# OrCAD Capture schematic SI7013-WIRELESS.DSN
size B; title: Si7013 wireless postage stamp; rev: 1.0; note: Si7013 Postage Stamp
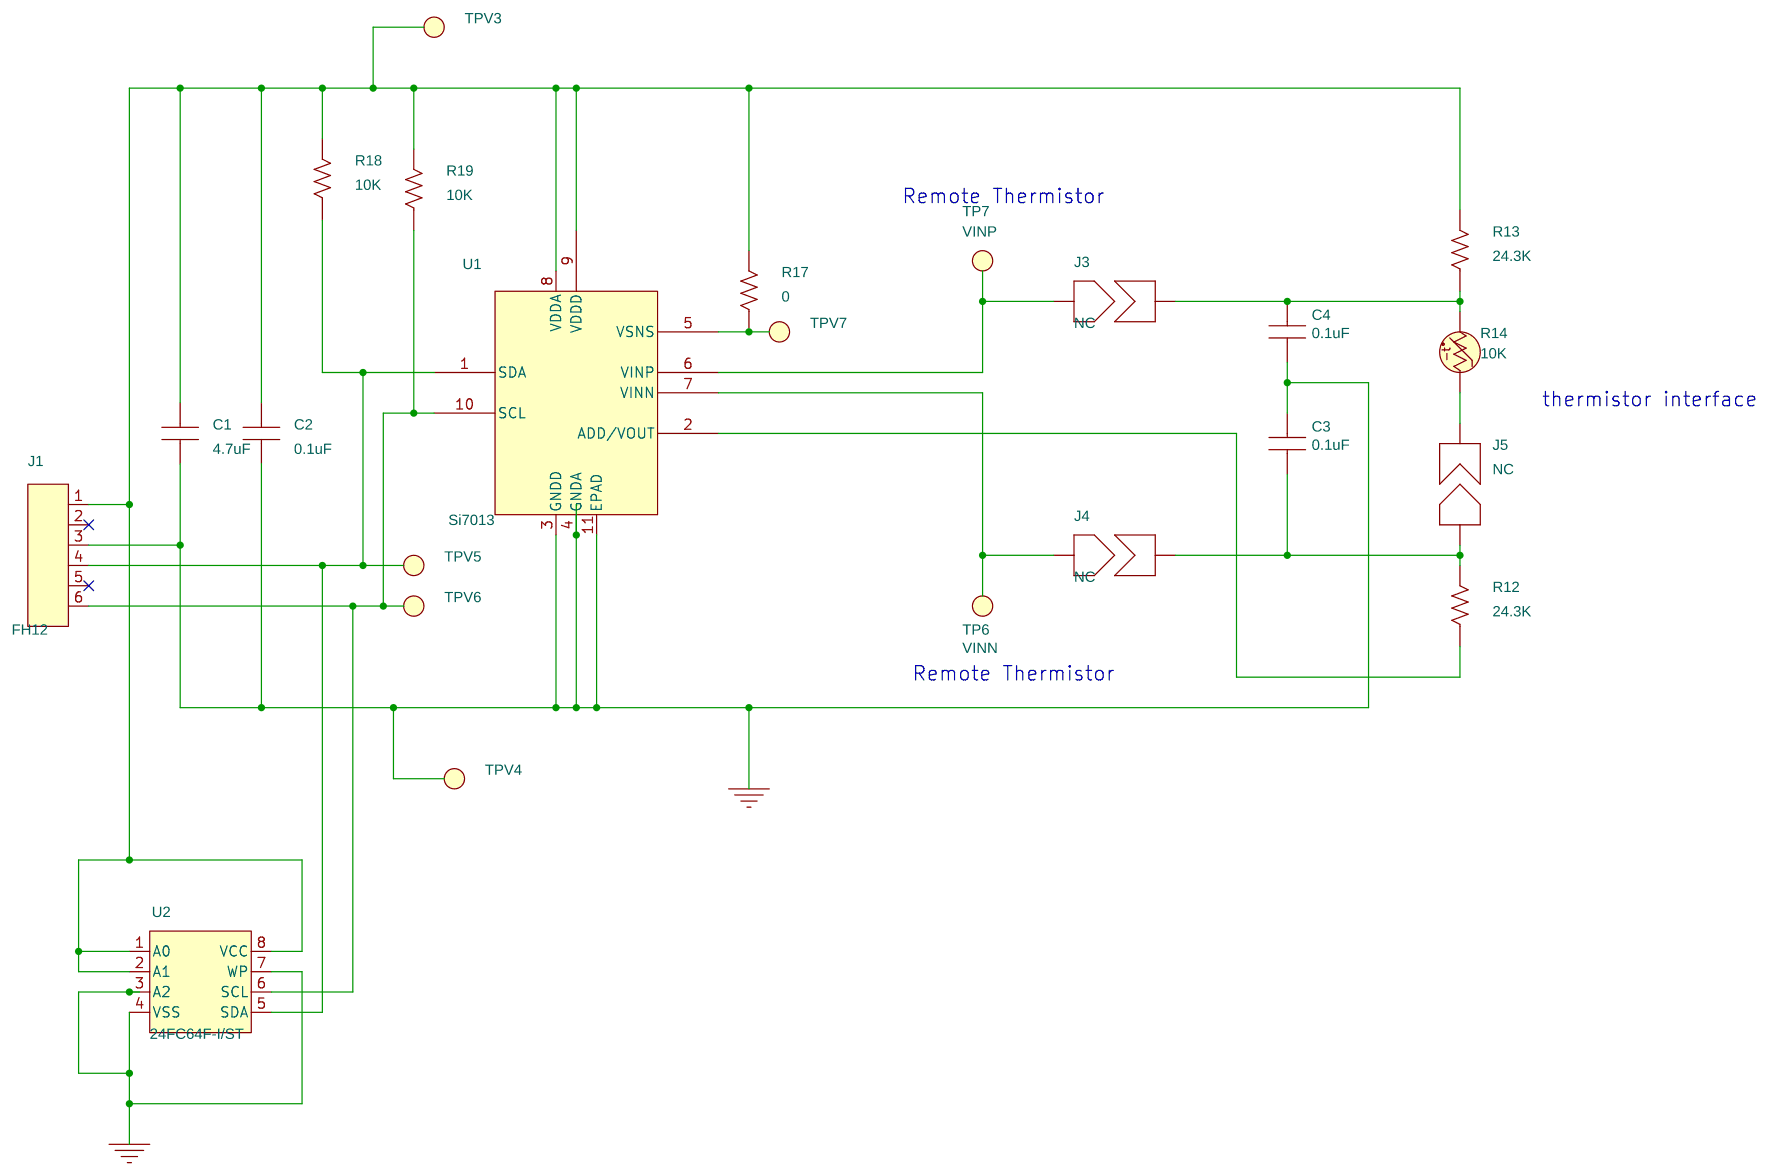
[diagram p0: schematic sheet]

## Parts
C1  4.7uF  [C0603]
C2  0.1uF  [C0402]
C3  0.1uF  [C0402]
C4  0.1uF  [C0402]
J1  FH12  [CONN6N-FPC/FFC-P0.5]
J3  NC  [SB0402-NC]
J4  NC  [SB0402-NC]
J5  NC  [SB0402-NC]
R12  24.3K  [R0603]
R13  24.3K  [R0603]
R14  10K  [R0603]
R17  0  [R0402]
R18  10K  [R0402]
R19  10K  [R0402]
TP6  BLACK  [TESTPOINT]
TP7  BLACK  [TESTPOINT]
TPV3  TPV  [VIA-TP]
TPV4  TPV  [VIA-TP]
TPV5  TPV  [VIA-TP]
TPV6  TPV  [VIA-TP]
TPV7  TPV  [VIA-TP]
U1  Si7013  [DFN10M3X3P0.5E1.4X2.6]
U2  24FC64F-I/ST  [TSSOP8N6.4P0.65]

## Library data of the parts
C1 = CAP_NP: CAP, 4.7uF, 6.3V, ±10%, X5R, 0603; Manufacturer: Venkel; ManufacturerPN: C0603X5R6R3-475K; Part_Type: CAP/NP; SiLabsPN: C0603X5R6R3-475K; Tolerance: ±10%; Type: X5R; Voltage: 6.3V; Datasheet: PID_C.pdf
C2 = CAP_NP: CAP, 0.1uF, 10V, ±10%, X7R, 0402; Manufacturer: Venkel; ManufacturerPN: C0402X7R100-104K; Part_Type: CAP/NP; SiLabsPN: C0402X7R100-104K; Tolerance: ±10%; Type: X7R; Voltage: 10V; Datasheet: PID_C.pdf
C3 C4 = CAP_NP: CAP, 0.1uF, 10V, ±20%, X7R, 0402; Manufacturer: Venkel; ManufacturerPN: C0402X7R100-104M; SiLabsPN: C0402X7R100-104M; Tolerance: ±20%; Type: X7R; Voltage: 10V; Datasheet: PID_C.pdf
J1 = CON6: CONN, 6-PIN , FPC/FFC, BOTTOM CONTACT, 0.5MM PITCH, SMD; Manufacturer: HIROSE; ManufacturerPN: FH12-6S-0.5SH(55); Part_Type: CON/MODULAR; SiLabsPN: FH12-6S-0.5SH(55); Datasheet: e58605370.pdf
J3-J5 = SolderBump: SOLDER BUMP JUMPER, NC, 0402; Manufacturer: N/A; ManufacturerPN: N/A; Type: PCB Feature
R12 R13 = RES: RES, 24.3K, 1/16W, ±1%, ThickFilm, 0603; Manufacturer: Venkel; ManufacturerPN: CR0603-16W-2432F; Rating: 1/16W; SiLabsPN: CR0603-16W-2432F; Tolerance: ±1%; Type: ThickFilm; Datasheet: PID_CR.pdf
R14 = Thermistor: Thermistor, 10K, ±1%, 0603; Manufacturer: Murata; ManufacturerPN: NCP18XH103F03RB; SiLabsPN: NCP18XH103F03RB; Tolerance: ±1%; Type: NTC; Datasheet: r44e.pdf
R17 = RES: RES, 0 Ohm, 1A, ThickFilm, 0402; Manufacturer: Venkel; ManufacturerPN: CR0402-16W-000; Rating: 1A; SiLabsPN: CR0402-16W-000; Type: ThickFilm; Datasheet: PID_CR.pdf
R18 R19 = RES: RES, 10K, 1/16W, ±1%, ThickFilm, 0402; Manufacturer: Venkel; ManufacturerPN: CR0402-16W-1002F; Rating: 1/16W; SiLabsPN: TMP-3686; Tolerance: ±1%; Type: ThickFilm; Datasheet: PID_CR.pdf
TP6 = TEST_POINT: TESTPOINT, BLACK, PTH; Manufacturer: Kobiconn; ManufacturerPN: 151-203-RC; SiLabsPN: 151-203; Silk: VINN; Type: Loop; Datasheet: KC-300780.pdf
TP7 = TEST_POINT: TESTPOINT, BLACK, PTH; Manufacturer: Kobiconn; ManufacturerPN: 151-203-RC; SiLabsPN: 151-203; Silk: VINP; Type: Loop; Datasheet: KC-300780.pdf
TPV3-TPV7 = TPV: TESTPOINT Via; Manufacturer: N/A; ManufacturerPN: N/A; Type: PCB Feature
U1 = Si7013: IC, SENSOR, HUMIDITY, DFN10; Manufacturer: SiLabs; ManufacturerPN: Si7013-A-GM; SiLabsPN: TMP-2779; Type: Sensor; Voltage: +4.2V; Datasheet: Si7013 Rev 0 2 draft 3 5 2013.pdf
U2 = 24FC64: IC, EEPROM, I2C, 64kb (8k x 8bit), 3 ADDR, 1MHz, TSSOP8; Manufacturer: Microchip; Type: I2C; Voltage: 3.3V; Datasheet: Microchip_24FC64.pdf

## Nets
GND: C1.1 C2.1 C3.1 C4.2 J1.3 TPV4.1(Point) U1.3(GNDD) U1.4(GNDA) U1.11(EPAD) U2.3(A2) U2.4(VSS) U2.7(WP)
N16761461: C1.2 C2.2 J1.1 R13.2 R17.2 R18.2 R19.2 TPV3.1(Point) U1.8(VDDA) U1.9(VDDD) U2.1(A0) U2.2(A1) U2.8(VCC)
N16761469: J1.4 R18.1 TPV5.1(Point) U1.1(SDA) U2.5(SDA)
N16761585: J1.6 R19.1 TPV6.1(Point) U1.10(SCL) U2.6(SCL)
N16768426: C4.1 J3.2(IO2) R13.1 R14.2
N16768430: C3.2 J4.2(IO2) J5.1(IO1) R12.2
N16768492: J5.2(IO2) R14.1
N16768496: R12.1 U1.2(ADD/VOUT)
N16768520: R17.1 TPV7.1(Point) U1.5(VSNS)
N16768726: J3.1(IO1) TP7.1(Point) U1.6(VINP)
N16768742: J4.1(IO1) TP6.1(Point) U1.7(VINN)

Not connected (* = marked no-connect by the designer): J1 2* 5*

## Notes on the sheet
- Remote Thermistor
- thermistor interface
- Remote Thermistor
